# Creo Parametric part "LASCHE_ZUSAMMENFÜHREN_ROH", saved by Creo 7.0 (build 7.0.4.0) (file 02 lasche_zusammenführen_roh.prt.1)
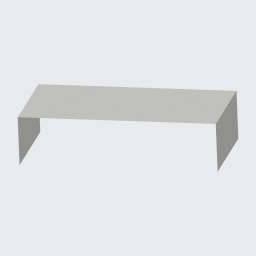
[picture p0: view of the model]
Units: millimeter Kilogram Sec (mmKs); MM, KILOGRAM, SECS
Materials in the file: S235JRG2

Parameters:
  PTC_MATERIAL_NAME = "S235JRG2"
  BENENNUNG = "XXX"
  DATUM = "XX.XX.XX"
  ERSTELLER = "ARINDA"
  TEILETYP = "Fertigungsteil"
  SELECT_EN_NAME = "S235JRG2"
  SELECT_DIN_NAME = "RSt37-2"
  SELECT_DIN_NUMBER = "1.0038"
  SELECT_ASTM_NAME = "A 283 M Grade 2"
  MATERIAL_GROUP = "ME_ST_Baustahl"
  STANDARD_EN_DELIVERYSPEC = "DIN EN 10025"
  STANDARD_DIN_DELIVERYSPEC = "DIN 17100"

Other parameters: MASSE

Created from: ARINDA-STARTTEIL.PRT

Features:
  1. coordinate system "CS0"
  2. datum plane "DTM1", "T_RECHTS_Y-Z"
  3. datum plane "DTM2", "T_OBEN_X-Z"
  4. datum plane "DTM3", "T_VORNE_X-Y"
  5. datum axis "T_X-ACHSE"
  6. datum axis "A_1"
  7. datum axis "A_2"
  8. feature "Profil 1"

Other named items: T_BASIC, T_Y-ACHSE, T_Z-ACHSE

Layers: 00_STD-ACHSEN, 00_STD-EBENEN, 00_STD-KOORDSYS, FLAECHEN, SAMMELFLÄCHEN

Surfaces: 5 plane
